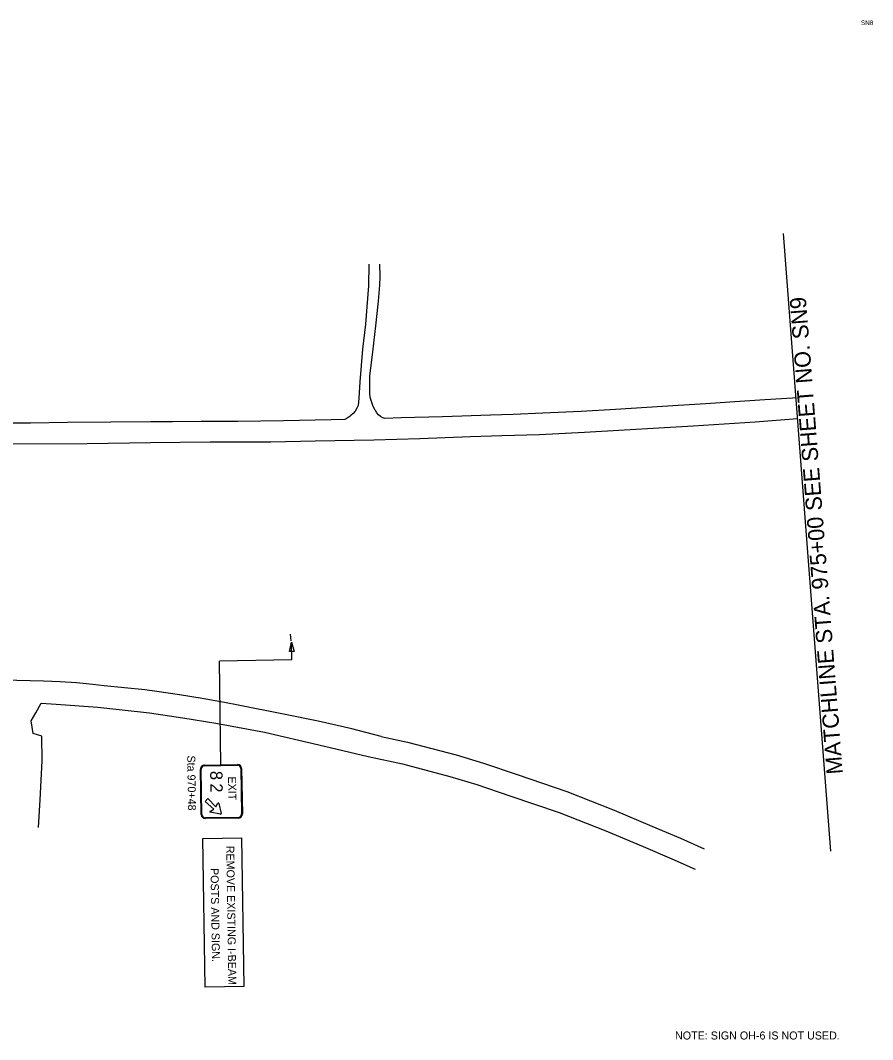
# Model space of a CAD drawing. Extents: x 1738744 to 1740331, y 1164386 to 1165340.
# Drawn here: x 1739586 to 1740331, y 1164449 to 1165340 of the extents above; entities that cross this region are included whole.
import ezdxf

# ---------------------------------------------------------------- set-up
doc = ezdxf.new("R2010")
doc.units = 0
for name, color, linetype in [('RD_EX_Driveway', 7, 'Continuous'), ('RD_EX_Road', 7, 'Continuous'), ('RD_SHT_MatchLine', 7, 'Continuous'), ('RD_SHT_TX', 7, 'Continuous'), ('SN_P_Signs', 7, 'Continuous')]:
    doc.layers.add(name, color=color, linetype=linetype)

msp = doc.modelspace()

# ---------------------------------------------------------------- linework, layer by layer
at = {"layer": 'RD_EX_Driveway'}
for points in [[(1739890.31, 1165126.97), (1739890.05, 1165107.94), (1739888.57, 1165089.49), (1739887.34, 1165074.3), (1739884.81, 1165052.56), (1739882.37, 1165023.97), (1739881.43, 1165009.59), (1739880.89, 1165003.37), (1739879.82, 1165000.82), (1739878.4, 1164998.45), (1739876.66, 1164996.31), (1739874.63, 1164994.44), (1739874.06, 1164994), (1739869.47, 1164991.06)], [(1739904.34, 1164991.88), (1739902.55, 1164992.51), (1739900.57, 1164993.64), (1739898.81, 1164995.08), (1739897.32, 1164996.81), (1739896.15, 1164998.77), (1739895.98, 1164999.14), (1739894.23, 1165002.44), (1739892.84, 1165005.91), (1739891.82, 1165009.5), (1739891.19, 1165013.18), (1739891.09, 1165014.05), (1739891.17, 1165028.84), (1739893.88, 1165050.26), (1739896.35, 1165072.86), (1739898.84, 1165094.42), (1739899.81, 1165108.65), (1739900.17, 1165116.15), (1739900.07, 1165126.81)]]:
    msp.add_lwpolyline(points, dxfattribs=at)
at = {"layer": 'RD_EX_Road'}
for points in [[(1740263.89, 1165010.12), (1740260.82, 1165009.84), (1740236.51, 1165008.24), (1740205.95, 1165006.07), (1740185.14, 1165004.82), (1740160.82, 1165003.29), (1740133.51, 1165001.62), (1740106.07, 1164999.72), (1740076.12, 1164998.1), (1740042.5, 1164996.64), (1740016.57, 1164995.51), (1739996.75, 1164994.94), (1739954.66, 1164993.37), (1739918.54, 1164992.42), (1739904.34, 1164991.88)], [(1739869.45, 1164991.06), (1739857.31, 1164990.87), (1739815.81, 1164989.91), (1739775.8, 1164989.37), (1739743.75, 1164989.21), (1739718.57, 1164989.06), (1739699.73, 1164988.86), (1739664.67, 1164988.7), (1739626.76, 1164988.4), (1739594.55, 1164987.78), (1739552.27, 1164987.92), (1739479.03, 1164986.3), (1739428.17, 1164985.09), (1739389.54, 1164983.5), (1739360.13, 1164982.79)], [(1740265.32, 1164991.69), (1740228.32, 1164988.61), (1740173.99, 1164985.33), (1740113.84, 1164981.66), (1740078.96, 1164979.66), (1740039.65, 1164977.58), (1740006.52, 1164976.65), (1739979.37, 1164975.83), (1739934.77, 1164974.22), (1739894.64, 1164972.94), (1739843.29, 1164972.06), (1739804.57, 1164971.31), (1739751.45, 1164971.08), (1739699.43, 1164970.69), (1739644.05, 1164969.79), (1739565.47, 1164969.59)], [(1739901.18, 1164713.91), (1739875.49, 1164720.4), (1739845.92, 1164727.33), (1739815.82, 1164733.48), (1739776, 1164741.26), (1739764.02, 1164743.63), (1739744.42, 1164747.19), (1739724.75, 1164750.36), (1739705.02, 1164753.14), (1739694.45, 1164754.5), (1739676.6, 1164756.48), (1739658.71, 1164758.07), (1739649.05, 1164759.24), (1739634.69, 1164760.65), (1739620.3, 1164761.66), (1739605.89, 1164762.28), (1739570.8, 1164763.18)], [(1739601.4, 1164634.27), (1739602.99, 1164658.57), (1739604.52, 1164692.52), (1739604.25, 1164714.01), (1739596.62, 1164716.52), (1739594.93, 1164727.4), (1739599.15, 1164734.67), (1739603.74, 1164742.95), (1739603.74, 1164742.95)], [(1739603.75, 1164742.95), (1739616.87, 1164742.21), (1739653.39, 1164739.53), (1739698.58, 1164734.5), (1739727.51, 1164730.19), (1739756.38, 1164725.49), (1739767.53, 1164723.57), (1739798.99, 1164717.63), (1739846.52, 1164706.52), (1739889.72, 1164696.44), (1739919.64, 1164689.95), (1739961.29, 1164678.92), (1739984.66, 1164671.92), (1740013.69, 1164662.07), (1740056.73, 1164647.32), (1740097.62, 1164631.23), (1740130.16, 1164617.53), (1740155.18, 1164606.9), (1740175.71, 1164597.76)], [(1739901.18, 1164713.91), (1739924.2, 1164708.91), (1739966.59, 1164697.69), (1739990.59, 1164690.5), (1740019.98, 1164680.53), (1740063.47, 1164665.63), (1740104.97, 1164649.29), (1740137.76, 1164635.49), (1740162.96, 1164624.79), (1740183.64, 1164615.58)]]:
    msp.add_lwpolyline(points, dxfattribs=at)
at = {"layer": 'RD_SHT_MatchLine'}
msp.add_lwpolyline([(1740294.49, 1164613.47), (1740272.85, 1164894.04), (1740252.83, 1165153.61)], dxfattribs=at)
at = {"layer": 'SN_P_Signs'}
for p, q in [((1739822.35, 1164797.59), (1739821.75, 1164803.44)), ((1739822.05, 1164800.51), (1739821.75, 1164803.44)), ((1739823.02, 1164780.83), (1739822.77, 1164796.44)), ((1739823.02, 1164780.83), (1739759.6, 1164779.84)), ((1739761.02, 1164689.11), (1739759.6, 1164779.84)), ((1739746.62, 1164688.88), (1739775.42, 1164689.33)), ((1739746.63, 1164688.28), (1739775.43, 1164688.73)), ((1739778.47, 1164685.78), (1739779.09, 1164646.19)), ((1739779.07, 1164685.79), (1739779.69, 1164646.19)), ((1739743.69, 1164645.63), (1739743.08, 1164685.23)), ((1739744.29, 1164645.64), (1739743.68, 1164685.24)), ((1739776.14, 1164643.14), (1739747.34, 1164642.69)), ((1739776.15, 1164642.54), (1739747.35, 1164642.09)), ((1739745.21, 1164624.65), (1739778.83, 1164625.17)), ((1739747.24, 1164494.65), (1739745.21, 1164624.65)), ((1739778.83, 1164625.17), (1739780.85, 1164495.17)), ((1739780.85, 1164495.17), (1739747.24, 1164494.65))]:
    msp.add_line(p, q, dxfattribs=at)
msp.add_lwpolyline([(1739820.85, 1164788.21), (1739822.77, 1164796.44), (1739824.95, 1164788.27)], close=True, dxfattribs=at)
for points in [[(1739747.12, 1164656.96), (1739749.62, 1164659.54), (1739756.53, 1164652.22)], [(1739754.65, 1164650.28), (1739747.12, 1164656.96)], [(1739751.53, 1164648.34), (1739754.65, 1164650.28)], [(1739756.53, 1164652.22), (1739758.37, 1164655.4)], [(1739759.2, 1164655.27), (1739761.09, 1164646.44)], [(1739760.57, 1164645.9), (1739751.69, 1164647.52)]]:
    msp.add_lwpolyline(points, dxfattribs=at)
for centre, radius, start, end in [((1739746.68, 1164685.28), 3.6, 90.89405, 180.89405), ((1739746.68, 1164685.28), 3, 90.89405, 180.89405), ((1739775.47, 1164685.73), 3.6, 0.89405, 90.89405), ((1739775.47, 1164685.73), 3, 0.89405, 90.89405), ((1739758.76, 1164655.18), 0.45, 12.07195, 149.85615), ((1739747.29, 1164645.69), 3.6, 180.89405, 270.89405), ((1739747.29, 1164645.69), 3, 180.89405, 270.89405), ((1739751.77, 1164647.96), 0.45, 121.93195, 259.71615), ((1739760.65, 1164646.35), 0.45, 259.71615, 12.07195), ((1739776.09, 1164646.14), 3, 270.89405, 0.89405), ((1739776.09, 1164646.14), 3.6, 270.89405, 0.89405)]:
    msp.add_arc(centre, radius, start, end, dxfattribs=at)

# ---------------------------------------------------------------- texts
at = {"layer": 'RD_SHT_TX'}
msp.add_text('SN8', height=4, dxfattribs=at).set_placement((1740320.73, 1165336))
msp.add_text('MATCHLINE STA. 975+00 SEE SHEET NO. SN9', height=14.1726, rotation=94.44329, dxfattribs=at).set_placement((1740304.88, 1164681.28))
at = {"layer": 'SN_P_Signs'}
for s, height, rotation, p in [('Sta 970+48', 7, 270.89413, (1739731.47, 1164697.16)), ('8', 10.8, 270.89405, (1739751.5, 1164683.69)), ('EXIT', 7, 270.89405, (1739767.18, 1164678.8)), ('2', 10.8, 270.89405, (1739751.67, 1164672.77)), ('REMOVE EXISTING I-BEAM', 7, 270.89413, (1739765.57, 1164618.21)), ('POSTS AND SIGN.', 7, 270.89413, (1739751.87, 1164598.76))]:
    msp.add_text(s, height=height, rotation=rotation, dxfattribs=at).set_placement(p)
msp.add_text('NOTE: SIGN OH-6 IS NOT USED.', height=7, dxfattribs=at).set_placement((1740158.11, 1164448.87))

doc.saveas('drawing.dxf')
